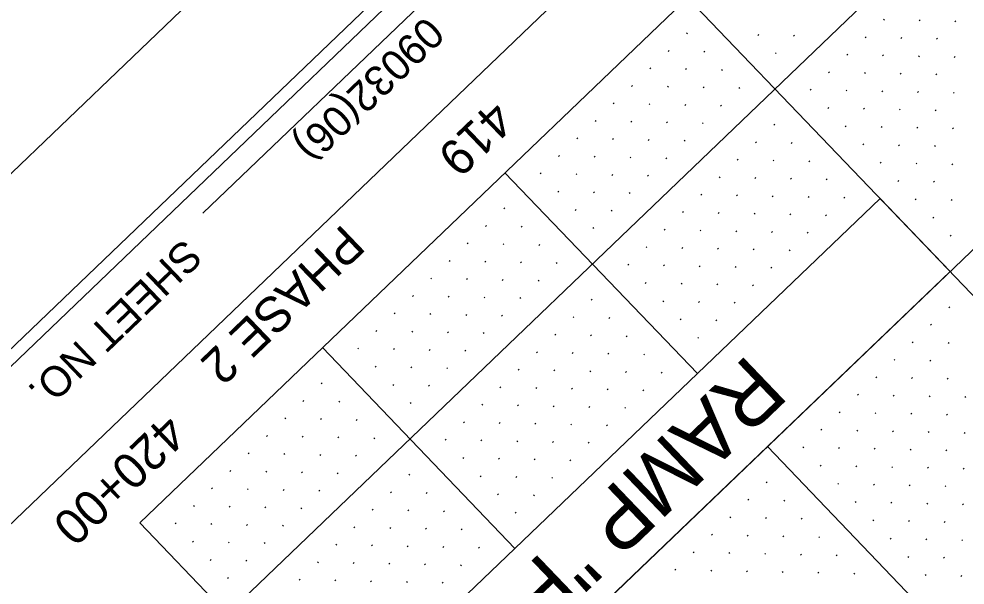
# Model space of a CAD drawing. Extents: x 2148987 to 2151117, y 142806 to 144993.
# Drawn here: x 2149110.7 to 2149297.8, y 143626.2 to 143738.1 of the extents above; entities that cross this region are included whole.
import ezdxf

# ---------------------------------------------------------------- set-up
doc = ezdxf.new("R2010")
doc.units = 0
for name, color, linetype in [('BASELINE', 7, 'Continuous'), ('PR_PIER_PH3', 7, 'Continuous'), ('PR_PIER_PH4', 7, 'Continuous'), ('PR_Road_Concrete', 7, 'Continuous'), ('PR_Slopewall_Ph4', 7, 'Continuous'), ('PR_Storm_Flow_Line', 7, 'Continuous'), ('SHT_Profile_Grid_Minor', 7, 'Continuous'), ('Wall D Bore Txt', 7, 'Continuous')]:
    doc.layers.add(name, color=color, linetype=linetype)

msp = doc.modelspace()

# ---------------------------------------------------------------- linework, layer by layer
at = {"layer": 'BASELINE'}
msp.add_lwpolyline([(2151029.45, 144024.32), (2149802.07, 142848.08), (2149040.98, 143642.27), (2150268.36, 144818.51)], close=True, dxfattribs=at)
at = {"layer": 'PR_PIER_PH3'}
for p, q in [((2150261.97, 144684.26), (2149124.83, 143594.52)), ((2150296.56, 144648.16), (2149159.43, 143558.42)), ((2149242.91, 143742.3), (2149540.43, 143431.84)), ((2149206.81, 143707.7), (2149244.86, 143667.99)), ((2149170.71, 143673.11), (2149208.76, 143633.4)), ((2149258.7, 143653.55), (2149504.33, 143397.25))]:
    msp.add_line(p, q, dxfattribs=at)
at = {"layer": 'PR_PIER_PH4'}
msp.add_line((2149199.59, 143750.04), (2149147.09, 143699.73), dxfattribs=at)
at = {"layer": 'PR_Road_Concrete'}
msp.add_line((2149134.61, 143638.51), (2149463.26, 143295.57), dxfattribs=at)
for points in [[(2150941.76, 143974.91), (2149804.63, 142885.16), (2149078.13, 143643.25), (2150215.26, 144733)], [(2149272.31, 143794.72), (2149256.75, 143810.96), (2149081.66, 143643.18), (2149097.23, 143626.93)], [(2149294.8, 143688.15), (2149280.96, 143702.59), (2149172.66, 143598.8), (2149186.5, 143584.36)]]:
    msp.add_lwpolyline(points, close=True, dxfattribs=at)
msp.add_lwpolyline([(2149279.76, 143812.24), (2149297.06, 143794.19), (2149134.61, 143638.51)], dxfattribs=at)
at = {"layer": 'SHT_Profile_Grid_Minor'}
for p, q in [((2149281.8, 143738.02), (2149281.62, 143737.85)), ((2149288.87, 143737.87), (2149288.69, 143737.7)), ((2149295.94, 143737.72), (2149295.76, 143737.55)), ((2149242.85, 143735.32), (2149242.67, 143735.14)), ((2149256.99, 143735.01), (2149256.81, 143734.84)), ((2149264.06, 143734.86), (2149263.88, 143734.69)), ((2149278.19, 143734.56), (2149278.01, 143734.39)), ((2149285.26, 143734.41), (2149285.08, 143734.24)), ((2149292.33, 143734.26), (2149292.15, 143734.09)), ((2149239.24, 143731.86), (2149239.06, 143731.68)), ((2149246.31, 143731.71), (2149246.13, 143731.53)), ((2149260.45, 143731.4), (2149260.27, 143731.23)), ((2149274.59, 143731.1), (2149274.4, 143730.93)), ((2149281.65, 143730.95), (2149281.47, 143730.78)), ((2149288.72, 143730.8), (2149288.54, 143730.63)), ((2149295.79, 143730.65), (2149295.61, 143730.48)), ((2149235.63, 143728.4), (2149235.45, 143728.22)), ((2149242.7, 143728.25), (2149242.52, 143728.07)), ((2149249.77, 143728.1), (2149249.59, 143727.92)), ((2149270.98, 143727.64), (2149270.79, 143727.47)), ((2149278.04, 143727.49), (2149277.86, 143727.32)), ((2149285.11, 143727.34), (2149284.93, 143727.17)), ((2149292.18, 143727.19), (2149292, 143727.02)), ((2149232.02, 143724.94), (2149231.84, 143724.76)), ((2149239.09, 143724.79), (2149238.91, 143724.61)), ((2149246.16, 143724.64), (2149245.98, 143724.46)), ((2149253.23, 143724.49), (2149253.05, 143724.31)), ((2149267.37, 143724.18), (2149267.18, 143724.01)), ((2149274.43, 143724.03), (2149274.25, 143723.86)), ((2149281.5, 143723.88), (2149281.32, 143723.71)), ((2149288.57, 143723.73), (2149288.39, 143723.56)), ((2149295.64, 143723.58), (2149295.46, 143723.41)), ((2149228.41, 143721.48), (2149228.23, 143721.3)), ((2149235.48, 143721.33), (2149235.3, 143721.15)), ((2149242.55, 143721.18), (2149242.37, 143721)), ((2149249.62, 143721.03), (2149249.44, 143720.85)), ((2149270.82, 143720.57), (2149270.64, 143720.4)), ((2149277.89, 143720.42), (2149277.71, 143720.25)), ((2149284.96, 143720.27), (2149284.78, 143720.1)), ((2149292.03, 143720.12), (2149291.85, 143719.95)), ((2149224.8, 143718.02), (2149224.62, 143717.85)), ((2149231.87, 143717.87), (2149231.69, 143717.69)), ((2149238.94, 143717.72), (2149238.76, 143717.54)), ((2149246.01, 143717.57), (2149245.83, 143717.39)), ((2149260.15, 143717.27), (2149259.96, 143717.09)), ((2149274.28, 143716.96), (2149274.1, 143716.79)), ((2149281.35, 143716.81), (2149281.17, 143716.64)), ((2149288.42, 143716.66), (2149288.24, 143716.49)), ((2149295.49, 143716.51), (2149295.31, 143716.34)), ((2149221.19, 143714.56), (2149221.01, 143714.39)), ((2149228.26, 143714.41), (2149228.08, 143714.24)), ((2149235.33, 143714.26), (2149235.15, 143714.08)), ((2149242.4, 143714.11), (2149242.22, 143713.93)), ((2149256.54, 143713.81), (2149256.35, 143713.63)), ((2149263.6, 143713.66), (2149263.42, 143713.48)), ((2149277.74, 143713.35), (2149277.56, 143713.18)), ((2149284.81, 143713.2), (2149284.63, 143713.03)), ((2149291.88, 143713.05), (2149291.7, 143712.88)), ((2149217.58, 143711.1), (2149217.4, 143710.93)), ((2149224.65, 143710.95), (2149224.47, 143710.78)), ((2149231.72, 143710.8), (2149231.54, 143710.63)), ((2149238.79, 143710.65), (2149238.61, 143710.47)), ((2149252.93, 143710.35), (2149252.74, 143710.17)), ((2149259.99, 143710.2), (2149259.81, 143710.02)), ((2149267.06, 143710.05), (2149266.88, 143709.87)), ((2149281.2, 143709.75), (2149281.02, 143709.57)), ((2149288.27, 143709.59), (2149288.09, 143709.42)), ((2149295.34, 143709.44), (2149295.16, 143709.27)), ((2149213.97, 143707.64), (2149213.79, 143707.47)), ((2149221.04, 143707.49), (2149220.86, 143707.32)), ((2149228.11, 143707.34), (2149227.93, 143707.17)), ((2149235.18, 143707.19), (2149235, 143707.02)), ((2149249.32, 143706.89), (2149249.13, 143706.71)), ((2149256.38, 143706.74), (2149256.2, 143706.56)), ((2149263.45, 143706.59), (2149263.27, 143706.41)), ((2149270.52, 143706.44), (2149270.34, 143706.26)), ((2149284.66, 143706.14), (2149284.48, 143705.96)), ((2149291.73, 143705.98), (2149291.55, 143705.81)), ((2149217.43, 143704.03), (2149217.25, 143703.86)), ((2149224.5, 143703.88), (2149224.32, 143703.71)), ((2149231.57, 143703.73), (2149231.39, 143703.56)), ((2149245.71, 143703.43), (2149245.52, 143703.25)), ((2149252.77, 143703.28), (2149252.59, 143703.1)), ((2149259.84, 143703.13), (2149259.66, 143702.95)), ((2149266.91, 143702.98), (2149266.73, 143702.8)), ((2149273.98, 143702.83), (2149273.8, 143702.65)), ((2149288.12, 143702.53), (2149287.94, 143702.35)), ((2149295.19, 143702.37), (2149295.01, 143702.2)), ((2149206.75, 143700.72), (2149206.57, 143700.55)), ((2149220.89, 143700.42), (2149220.71, 143700.25)), ((2149227.96, 143700.27), (2149227.78, 143700.1)), ((2149242.1, 143699.97), (2149241.91, 143699.8)), ((2149249.16, 143699.82), (2149248.98, 143699.64)), ((2149256.23, 143699.67), (2149256.05, 143699.49)), ((2149263.3, 143699.52), (2149263.12, 143699.34)), ((2149270.37, 143699.37), (2149270.19, 143699.19)), ((2149291.58, 143698.92), (2149291.4, 143698.74)), ((2149203.14, 143697.26), (2149202.96, 143697.09)), ((2149210.21, 143697.11), (2149210.03, 143696.94)), ((2149224.35, 143696.81), (2149224.17, 143696.64)), ((2149238.49, 143696.51), (2149238.31, 143696.34)), ((2149245.55, 143696.36), (2149245.37, 143696.19)), ((2149252.62, 143696.21), (2149252.44, 143696.03)), ((2149259.69, 143696.06), (2149259.51, 143695.88)), ((2149266.76, 143695.91), (2149266.58, 143695.73)), ((2149199.53, 143693.8), (2149199.35, 143693.63)), ((2149295.04, 143695.31), (2149294.86, 143695.13)), ((2149206.6, 143693.65), (2149206.42, 143693.48)), ((2149213.67, 143693.5), (2149213.49, 143693.33)), ((2149234.88, 143693.05), (2149234.7, 143692.88)), ((2149241.95, 143692.9), (2149241.76, 143692.73)), ((2149249.01, 143692.75), (2149248.83, 143692.58)), ((2149256.08, 143692.6), (2149255.9, 143692.42)), ((2149263.15, 143692.45), (2149262.97, 143692.27)), ((2149195.92, 143690.34), (2149195.74, 143690.17)), ((2149202.99, 143690.19), (2149202.81, 143690.02)), ((2149210.06, 143690.04), (2149209.88, 143689.87)), ((2149217.13, 143689.89), (2149216.95, 143689.72)), ((2149231.27, 143689.59), (2149231.09, 143689.42)), ((2149238.34, 143689.44), (2149238.15, 143689.27)), ((2149245.4, 143689.29), (2149245.22, 143689.12)), ((2149252.47, 143689.14), (2149252.29, 143688.97)), ((2149259.54, 143688.99), (2149259.36, 143688.81)), ((2149192.31, 143686.88), (2149192.13, 143686.71)), ((2149199.38, 143686.73), (2149199.2, 143686.56)), ((2149206.45, 143686.58), (2149206.27, 143686.41)), ((2149213.52, 143686.43), (2149213.34, 143686.26)), ((2149234.73, 143685.98), (2149234.54, 143685.81)), ((2149241.79, 143685.83), (2149241.61, 143685.66)), ((2149248.86, 143685.68), (2149248.68, 143685.51)), ((2149255.93, 143685.53), (2149255.75, 143685.36)), ((2149188.7, 143683.42), (2149188.52, 143683.25)), ((2149195.77, 143683.27), (2149195.59, 143683.1)), ((2149202.84, 143683.12), (2149202.66, 143682.95)), ((2149209.91, 143682.97), (2149209.73, 143682.8)), ((2149224.05, 143682.67), (2149223.87, 143682.5)), ((2149238.18, 143682.37), (2149238, 143682.2)), ((2149245.25, 143682.22), (2149245.07, 143682.05)), ((2149252.32, 143682.07), (2149252.14, 143681.9)), ((2149294.74, 143681.17), (2149294.56, 143680.99)), ((2149185.09, 143679.96), (2149184.91, 143679.79)), ((2149192.16, 143679.81), (2149191.98, 143679.64)), ((2149199.23, 143679.66), (2149199.05, 143679.49)), ((2149206.3, 143679.51), (2149206.12, 143679.34)), ((2149220.44, 143679.21), (2149220.26, 143679.04)), ((2149227.51, 143679.06), (2149227.32, 143678.89)), ((2149241.64, 143678.76), (2149241.46, 143678.59)), ((2149248.71, 143678.61), (2149248.53, 143678.44)), ((2149291.13, 143677.71), (2149290.95, 143677.53)), ((2149181.48, 143676.5), (2149181.3, 143676.33)), ((2149188.55, 143676.35), (2149188.37, 143676.18)), ((2149195.62, 143676.2), (2149195.44, 143676.03)), ((2149202.69, 143676.05), (2149202.51, 143675.88)), ((2149216.83, 143675.75), (2149216.65, 143675.58)), ((2149223.9, 143675.6), (2149223.71, 143675.43)), ((2149230.96, 143675.45), (2149230.78, 143675.28)), ((2149245.1, 143675.15), (2149244.92, 143674.98)), ((2149287.52, 143674.25), (2149287.34, 143674.07)), ((2149294.59, 143674.1), (2149294.41, 143673.92)), ((2149177.87, 143673.04), (2149177.69, 143672.87)), ((2149184.94, 143672.89), (2149184.76, 143672.72)), ((2149192.01, 143672.74), (2149191.83, 143672.57)), ((2149199.08, 143672.59), (2149198.9, 143672.42)), ((2149213.22, 143672.29), (2149213.04, 143672.12)), ((2149220.29, 143672.14), (2149220.1, 143671.97)), ((2149227.35, 143671.99), (2149227.17, 143671.82)), ((2149234.42, 143671.84), (2149234.24, 143671.67)), ((2149181.33, 143669.43), (2149181.15, 143669.26)), ((2149283.91, 143670.79), (2149283.73, 143670.61)), ((2149290.98, 143670.64), (2149290.8, 143670.46)), ((2149188.4, 143669.28), (2149188.22, 143669.11)), ((2149195.47, 143669.13), (2149195.29, 143668.96)), ((2149209.61, 143668.83), (2149209.43, 143668.66)), ((2149216.68, 143668.68), (2149216.49, 143668.51)), ((2149223.74, 143668.53), (2149223.56, 143668.36)), ((2149230.81, 143668.38), (2149230.63, 143668.21)), ((2149237.88, 143668.23), (2149237.7, 143668.06)), ((2149170.65, 143666.13), (2149170.47, 143665.95)), ((2149184.79, 143665.82), (2149184.61, 143665.65)), ((2149280.3, 143667.33), (2149280.12, 143667.16)), ((2149287.37, 143667.18), (2149287.19, 143667)), ((2149294.44, 143667.03), (2149294.26, 143666.85)), ((2149191.86, 143665.67), (2149191.68, 143665.5)), ((2149206, 143665.37), (2149205.82, 143665.2)), ((2149213.07, 143665.22), (2149212.88, 143665.05)), ((2149220.13, 143665.07), (2149219.95, 143664.9)), ((2149227.2, 143664.92), (2149227.02, 143664.75)), ((2149234.27, 143664.77), (2149234.09, 143664.6)), ((2149276.69, 143663.87), (2149276.51, 143663.7)), ((2149167.04, 143662.67), (2149166.86, 143662.49)), ((2149174.11, 143662.52), (2149173.93, 143662.34)), ((2149188.25, 143662.21), (2149188.07, 143662.04)), ((2149283.76, 143663.72), (2149283.58, 143663.55)), ((2149290.83, 143663.57), (2149290.65, 143663.39)), ((2149297.9, 143663.42), (2149297.72, 143663.24)), ((2149202.39, 143661.91), (2149202.21, 143661.74)), ((2149209.46, 143661.76), (2149209.27, 143661.59)), ((2149216.52, 143661.61), (2149216.34, 143661.44)), ((2149223.59, 143661.46), (2149223.41, 143661.29)), ((2149230.66, 143661.31), (2149230.48, 143661.14)), ((2149273.08, 143660.41), (2149272.9, 143660.24)), ((2149280.15, 143660.26), (2149279.97, 143660.09)), ((2149287.22, 143660.11), (2149287.04, 143659.94)), ((2149163.43, 143659.21), (2149163.25, 143659.03)), ((2149170.5, 143659.06), (2149170.32, 143658.88)), ((2149177.57, 143658.91), (2149177.39, 143658.73)), ((2149198.78, 143658.45), (2149198.6, 143658.28)), ((2149205.85, 143658.3), (2149205.66, 143658.13)), ((2149294.29, 143659.96), (2149294.11, 143659.78)), ((2149212.91, 143658.15), (2149212.73, 143657.98)), ((2149219.98, 143658), (2149219.8, 143657.83)), ((2149227.05, 143657.85), (2149226.87, 143657.68)), ((2149269.47, 143656.95), (2149269.29, 143656.78)), ((2149276.54, 143656.8), (2149276.36, 143656.63)), ((2149283.61, 143656.65), (2149283.43, 143656.48)), ((2149290.68, 143656.5), (2149290.5, 143656.33)), ((2149297.75, 143656.35), (2149297.57, 143656.17)), ((2149159.82, 143655.75), (2149159.64, 143655.57)), ((2149166.89, 143655.6), (2149166.71, 143655.42)), ((2149173.96, 143655.45), (2149173.78, 143655.27)), ((2149181.03, 143655.3), (2149180.85, 143655.12)), ((2149195.17, 143654.99), (2149194.99, 143654.82)), ((2149202.24, 143654.84), (2149202.06, 143654.67)), ((2149209.3, 143654.69), (2149209.12, 143654.52)), ((2149216.37, 143654.54), (2149216.19, 143654.37)), ((2149223.44, 143654.39), (2149223.26, 143654.22)), ((2149265.86, 143653.49), (2149265.68, 143653.32)), ((2149272.93, 143653.34), (2149272.75, 143653.17)), ((2149280, 143653.19), (2149279.82, 143653.02)), ((2149287.07, 143653.04), (2149286.89, 143652.87)), ((2149294.14, 143652.89), (2149293.96, 143652.72)), ((2149156.21, 143652.29), (2149156.03, 143652.11)), ((2149163.28, 143652.14), (2149163.1, 143651.96)), ((2149170.35, 143651.99), (2149170.17, 143651.81)), ((2149177.42, 143651.84), (2149177.24, 143651.66)), ((2149198.63, 143651.38), (2149198.45, 143651.21)), ((2149205.7, 143651.23), (2149205.51, 143651.06)), ((2149212.76, 143651.08), (2149212.58, 143650.91)), ((2149219.83, 143650.93), (2149219.65, 143650.76)), ((2149269.32, 143649.88), (2149269.14, 143649.71)), ((2149276.39, 143649.73), (2149276.21, 143649.56)), ((2149283.46, 143649.58), (2149283.28, 143649.41)), ((2149290.53, 143649.43), (2149290.35, 143649.26)), ((2149297.6, 143649.28), (2149297.42, 143649.11)), ((2149152.6, 143648.83), (2149152.42, 143648.65)), ((2149159.67, 143648.68), (2149159.49, 143648.5)), ((2149166.74, 143648.53), (2149166.56, 143648.35)), ((2149173.81, 143648.38), (2149173.63, 143648.2)), ((2149187.95, 143648.08), (2149187.77, 143647.9)), ((2149202.09, 143647.77), (2149201.9, 143647.6)), ((2149209.15, 143647.62), (2149208.97, 143647.45)), ((2149216.22, 143647.47), (2149216.04, 143647.3)), ((2149148.99, 143645.37), (2149148.81, 143645.2)), ((2149156.06, 143645.22), (2149155.88, 143645.04)), ((2149258.64, 143646.57), (2149258.46, 143646.4)), ((2149272.78, 143646.27), (2149272.6, 143646.1)), ((2149279.85, 143646.12), (2149279.67, 143645.95)), ((2149286.92, 143645.97), (2149286.74, 143645.8)), ((2149293.99, 143645.82), (2149293.81, 143645.65)), ((2149163.13, 143645.07), (2149162.95, 143644.89)), ((2149170.2, 143644.92), (2149170.02, 143644.74)), ((2149184.34, 143644.62), (2149184.16, 143644.44)), ((2149191.41, 143644.47), (2149191.23, 143644.29)), ((2149205.54, 143644.16), (2149205.36, 143643.99)), ((2149212.61, 143644.01), (2149212.43, 143643.84)), ((2149145.38, 143641.91), (2149145.2, 143641.74)), ((2149152.45, 143641.76), (2149152.27, 143641.59)), ((2149159.52, 143641.61), (2149159.34, 143641.43)), ((2149166.59, 143641.46), (2149166.41, 143641.28)), ((2149255.03, 143643.11), (2149254.85, 143642.94)), ((2149262.1, 143642.96), (2149261.92, 143642.79)), ((2149276.24, 143642.66), (2149276.06, 143642.49)), ((2149283.31, 143642.51), (2149283.13, 143642.34)), ((2149290.38, 143642.36), (2149290.2, 143642.19)), ((2149297.45, 143642.21), (2149297.27, 143642.04)), ((2149180.73, 143641.16), (2149180.55, 143640.98)), ((2149187.8, 143641.01), (2149187.62, 143640.83)), ((2149194.87, 143640.86), (2149194.68, 143640.68)), ((2149209, 143640.55), (2149208.82, 143640.38)), ((2149251.42, 143639.65), (2149251.24, 143639.48)), ((2149258.49, 143639.5), (2149258.31, 143639.33)), ((2149141.77, 143638.45), (2149141.59, 143638.28)), ((2149148.84, 143638.3), (2149148.66, 143638.13)), ((2149155.91, 143638.15), (2149155.73, 143637.98)), ((2149162.98, 143638), (2149162.8, 143637.82)), ((2149177.12, 143637.7), (2149176.94, 143637.52)), ((2149265.56, 143639.35), (2149265.38, 143639.18)), ((2149279.7, 143639.05), (2149279.52, 143638.88)), ((2149286.77, 143638.9), (2149286.59, 143638.73)), ((2149293.84, 143638.75), (2149293.66, 143638.58)), ((2149184.19, 143637.55), (2149184.01, 143637.37)), ((2149191.26, 143637.4), (2149191.07, 143637.22)), ((2149198.32, 143637.25), (2149198.14, 143637.07)), ((2149247.81, 143636.19), (2149247.63, 143636.02)), ((2149254.88, 143636.04), (2149254.7, 143635.87)), ((2149261.95, 143635.89), (2149261.77, 143635.72)), ((2149145.23, 143634.84), (2149145.05, 143634.67)), ((2149152.3, 143634.69), (2149152.12, 143634.52)), ((2149159.37, 143634.54), (2149159.19, 143634.37)), ((2149173.51, 143634.24), (2149173.33, 143634.06)), ((2149180.58, 143634.09), (2149180.4, 143633.91)), ((2149187.65, 143633.94), (2149187.46, 143633.76)), ((2149269.02, 143635.74), (2149268.84, 143635.57)), ((2149283.16, 143635.44), (2149282.98, 143635.27)), ((2149290.23, 143635.29), (2149290.05, 143635.12)), ((2149297.3, 143635.14), (2149297.12, 143634.97)), ((2149194.71, 143633.79), (2149194.53, 143633.61)), ((2149201.78, 143633.64), (2149201.6, 143633.46)), ((2149244.2, 143632.73), (2149244.02, 143632.56)), ((2149251.27, 143632.58), (2149251.09, 143632.41)), ((2149258.34, 143632.43), (2149258.16, 143632.26)), ((2149265.41, 143632.28), (2149265.23, 143632.11)), ((2149272.48, 143632.13), (2149272.3, 143631.96)), ((2149148.69, 143631.23), (2149148.51, 143631.06)), ((2149155.76, 143631.08), (2149155.58, 143630.91)), ((2149169.9, 143630.78), (2149169.72, 143630.6)), ((2149176.97, 143630.63), (2149176.79, 143630.45)), ((2149184.04, 143630.48), (2149183.85, 143630.3)), ((2149191.1, 143630.33), (2149190.92, 143630.15)), ((2149198.17, 143630.18), (2149197.99, 143630)), ((2149286.62, 143631.83), (2149286.44, 143631.66)), ((2149293.69, 143631.68), (2149293.51, 143631.51)), ((2149240.59, 143629.27), (2149240.41, 143629.1)), ((2149247.66, 143629.12), (2149247.48, 143628.95)), ((2149254.73, 143628.97), (2149254.55, 143628.8)), ((2149261.8, 143628.82), (2149261.62, 143628.65)), ((2149268.87, 143628.67), (2149268.69, 143628.5)), ((2149275.94, 143628.52), (2149275.76, 143628.35)), ((2149152.15, 143627.62), (2149151.97, 143627.45)), ((2149166.29, 143627.32), (2149166.11, 143627.15)), ((2149173.36, 143627.17), (2149173.18, 143626.99)), ((2149180.43, 143627.02), (2149180.24, 143626.84)), ((2149187.49, 143626.87), (2149187.31, 143626.69)), ((2149194.56, 143626.72), (2149194.38, 143626.54)), ((2149290.08, 143628.22), (2149289.9, 143628.05)), ((2149297.15, 143628.07), (2149296.97, 143627.9))]:
    msp.add_line(p, q, dxfattribs=at)

# ---------------------------------------------------------------- texts
at = {"layer": 'PR_Slopewall_Ph4'}
for s, height, p in [('09032(06)', 6, (2149191.17, 143738.86)), ('PHASE 2', 7, (2149174.76, 143697.73)), ('SHEET NO.', 6, (2149143.31, 143694.9))]:
    msp.add_text(s, height=height, rotation=223.7809, dxfattribs=at).set_placement(p)
at = {"layer": 'PR_Storm_Flow_Line'}
msp.add_text('RAMP "F"', height=12, rotation=223.7809, dxfattribs=at).set_placement((2149254.9, 143672.07))
at = {"layer": 'Wall D Bore Txt'}
for s, p in [('419', (2149204.36, 143722.32)), ('420+00', (2149139.68, 143660.34))]:
    msp.add_text(s, height=7, rotation=223.7809, dxfattribs=at).set_placement(p)

doc.saveas('drawing.dxf')
